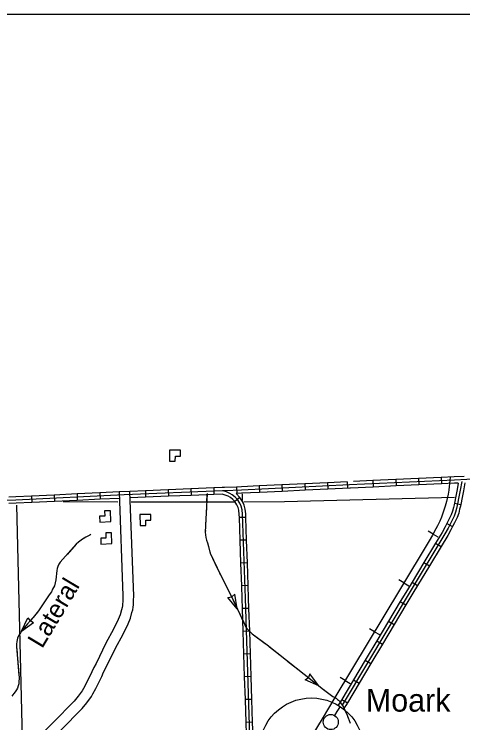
# Model space of a CAD drawing. Extents: x 1164457 to 1439835, y 1590918 to 1773502.
# Drawn here: x 1308056 to 1318450, y 1662145 to 1678582 of the extents above; entities that cross this region are included whole.
import ezdxf

# ---------------------------------------------------------------- set-up
doc = ezdxf.new("R2010")
doc.units = 0
for name, color, linetype in [('Level 15', 7, 'Continuous'), ('Level 24', 7, 'Continuous'), ('Level 32', 7, 'Continuous'), ('Level 4', 7, 'Continuous'), ('Level 40', 7, 'Continuous'), ('Level 43', 7, 'Continuous'), ('Level 5', 7, 'Continuous'), ('Level 58', 7, 'Continuous'), ('Level 63', 7, 'Continuous'), ('R_Draft', 7, 'Continuous')]:
    doc.layers.add(name, color=color, linetype=linetype)

msp = doc.modelspace()

# ---------------------------------------------------------------- linework, layer by layer
at = {"layer": 'Level 15'}
for points in [[(1310735, 1667512), (1310486, 1667501), (1310577, 1665087), (1310573, 1664999), (1310572, 1664954), (1310569, 1664906), (1310564, 1664860), (1310557, 1664818), (1310544, 1664765), (1310512, 1664653), (1310467, 1664540), (1310358, 1664316), (1310183, 1663994), (1309952, 1663519), (1309902, 1663427), (1309857, 1663325), (1309726, 1663054), (1309664, 1662942), (1309634, 1662890), (1309542, 1662760), (1309448, 1662647), (1308959, 1662152), (1307801, 1660969), (1308163, 1660982)], [(1308163, 1660982), (1309138, 1661977), (1309634, 1662478), (1309741, 1662607), (1309845, 1662755), (1309882, 1662819), (1309948, 1662939), (1310084, 1663220), (1310127, 1663317), (1310174, 1663405), (1310405, 1663880), (1310580, 1664202), (1310696, 1664438), (1310749, 1664572), (1310785, 1664701), (1310802, 1664768), (1310812, 1664827), (1310818, 1664884), (1310822, 1664943), (1310822, 1664992), (1310828, 1665085), (1310735, 1667512)]]:
    msp.add_lwpolyline(points, dxfattribs=at)
at = {"layer": 'Level 24'}
msp.add_circle((1315391, 1662163), 175, dxfattribs=at)
at = {"layer": 'Level 32'}
for p, q in [((1314787, 1667690), (1314794, 1667540)), ((1315314, 1667715), (1315321, 1667565)), ((1315768, 1667737), (1315775, 1667587)), ((1316369, 1667765), (1316376, 1667615)), ((1316897, 1667789), (1316903, 1667639)), ((1317424, 1667813), (1317431, 1667663)), ((1317952, 1667837), (1317958, 1667687)), ((1311095, 1667527), (1311101, 1667377)), ((1311622, 1667549), (1311629, 1667399)), ((1312150, 1667571), (1312156, 1667421)), ((1312678, 1667593), (1312684, 1667443)), ((1313205, 1667614), (1313211, 1667464)), ((1313732, 1667639), (1313739, 1667489)), ((1314259, 1667664), (1314267, 1667514)), ((1308457, 1667404), (1308464, 1667254)), ((1308985, 1667429), (1308992, 1667280)), ((1309512, 1667455), (1309519, 1667305)), ((1310039, 1667480), (1310047, 1667330)), ((1313286, 1667371), (1313168, 1667277)), ((1318256, 1667242), (1318402, 1667207)), ((1313424, 1666911), (1313274, 1666906)), ((1318080, 1666765), (1318214, 1666698)), ((1313441, 1666383), (1313292, 1666378)), ((1317821, 1666312), (1317949, 1666235)), ((1313459, 1665855), (1313309, 1665850)), ((1317547, 1665861), (1317675, 1665783)), ((1317273, 1665409), (1317402, 1665331)), ((1313477, 1665328), (1313327, 1665322)), ((1317001, 1664956), (1317130, 1664879)), ((1313494, 1664800), (1313344, 1664795)), ((1316731, 1664503), (1316860, 1664426)), ((1313512, 1664272), (1313362, 1664267)), ((1316460, 1664049), (1316589, 1663972)), ((1313529, 1663744), (1313379, 1663739)), ((1316190, 1663596), (1316318, 1663519)), ((1313546, 1663217), (1313396, 1663212)), ((1315919, 1663143), (1316048, 1663066)), ((1313563, 1662689), (1313413, 1662684)), ((1315648, 1662689), (1315777, 1662612)), ((1313580, 1662161), (1313431, 1662156))]:
    msp.add_line(p, q, dxfattribs=at)
for points in [[(1321119, 1667917), (1318832, 1667801), (1318254, 1667775), (1315826, 1667665), (1313323, 1667544), (1312931, 1667528), (1312880, 1667526), (1310607, 1667432), (1308095, 1667312), (1306907, 1667268), (1305501, 1667210), (1305435, 1667209), (1305218, 1667203), (1302807, 1667104), (1300037, 1666964), (1300001, 1666961)], [(1318479, 1667860), (1318251, 1667850), (1317952, 1667837)], [(1314787, 1667690), (1314259, 1667664)], [(1315314, 1667715), (1314787, 1667690)], [(1315768, 1667737), (1315314, 1667715)], [(1318424, 1667744), (1318392, 1667540), (1318354, 1667350), (1318338, 1667262), (1318320, 1667187), (1318304, 1667119), (1318283, 1667032), (1318248, 1666938), (1318188, 1666814), (1318110, 1666658), (1318037, 1666525), (1317230, 1665193), (1315703, 1662634), (1315655, 1662557)], [(1316369, 1667765), (1315918, 1667744)], [(1316897, 1667789), (1316369, 1667765)], [(1317424, 1667813), (1316897, 1667789)], [(1317952, 1667837), (1317424, 1667813)], [(1318342, 1667704), (1318258, 1667701), (1317958, 1667687)], [(1318342, 1667704), (1318318, 1667554), (1318280, 1667364), (1318264, 1667278), (1318256, 1667242)], [(1318494, 1667711), (1318466, 1667527), (1318427, 1667335), (1318411, 1667247), (1318402, 1667207)], [(1311095, 1667527), (1310735, 1667512)], [(1311622, 1667549), (1311095, 1667527)], [(1312150, 1667571), (1311622, 1667549)], [(1312678, 1667593), (1312150, 1667571)], [(1313205, 1667614), (1312928, 1667603), (1312878, 1667601), (1312678, 1667593)], [(1313540, 1661103), (1313412, 1665035), (1313346, 1666984), (1313336, 1667088), (1313314, 1667167), (1313281, 1667242), (1313227, 1667324), (1313175, 1667379), (1313107, 1667431), (1313050, 1667466), (1312974, 1667500), (1312880, 1667526)], [(1313732, 1667639), (1313320, 1667619), (1313205, 1667614)], [(1314259, 1667664), (1313732, 1667639)], [(1314794, 1667540), (1314267, 1667514)], [(1315321, 1667565), (1314794, 1667540)], [(1315849, 1667591), (1315830, 1667590), (1315321, 1667565)], [(1316376, 1667615), (1315849, 1667591)], [(1316903, 1667639), (1316376, 1667615)], [(1317431, 1667663), (1316903, 1667639)], [(1317958, 1667687), (1317431, 1667663)], [(1308457, 1667404), (1308092, 1667387), (1307931, 1667381)], [(1308985, 1667429), (1308457, 1667404)], [(1309512, 1667455), (1308985, 1667429)], [(1310039, 1667480), (1309512, 1667455)], [(1310486, 1667501), (1310039, 1667480)], [(1311101, 1667377), (1310741, 1667363)], [(1311629, 1667399), (1311101, 1667377)], [(1312156, 1667421), (1311629, 1667399)], [(1312684, 1667443), (1312156, 1667421)], [(1312872, 1667451), (1312684, 1667443)], [(1313121, 1667325), (1313065, 1667369), (1313015, 1667400), (1312948, 1667429), (1312872, 1667451)], [(1313739, 1667489), (1313326, 1667469), (1313198, 1667464)], [(1313424, 1666911), (1313421, 1666989), (1313410, 1667102), (1313385, 1667193), (1313347, 1667278), (1313286, 1667371), (1313198, 1667464)], [(1314267, 1667514), (1313739, 1667489)], [(1308464, 1667254), (1308099, 1667237), (1307936, 1667231)], [(1308992, 1667280), (1308464, 1667254)], [(1309519, 1667305), (1308992, 1667280)], [(1310047, 1667330), (1309519, 1667305)], [(1310491, 1667351), (1310047, 1667330)], [(1313274, 1666906), (1313271, 1666979), (1313262, 1667074), (1313244, 1667142), (1313215, 1667205), (1313168, 1667277), (1313125, 1667323), (1313121, 1667325)], [(1318256, 1667242), (1318247, 1667204), (1318231, 1667136), (1318211, 1667054), (1318179, 1666967), (1318121, 1666847), (1318080, 1666765)], [(1318402, 1667207), (1318393, 1667170), (1318377, 1667102), (1318355, 1667010), (1318317, 1666908), (1318256, 1666781), (1318214, 1666698)], [(1313292, 1666378), (1313274, 1666906)], [(1313441, 1666383), (1313424, 1666911)], [(1318080, 1666765), (1318043, 1666693), (1317972, 1666562), (1317821, 1666312)], [(1318214, 1666698), (1318176, 1666623), (1318102, 1666487), (1317949, 1666235)], [(1313309, 1665850), (1313292, 1666378)], [(1313459, 1665855), (1313441, 1666383)], [(1317821, 1666312), (1317547, 1665861)], [(1317949, 1666235), (1317675, 1665783)], [(1313327, 1665322), (1313309, 1665850)], [(1313477, 1665328), (1313459, 1665855)], [(1317547, 1665861), (1317273, 1665409)], [(1317675, 1665783), (1317402, 1665331)], [(1317273, 1665409), (1317166, 1665232), (1317001, 1664956)], [(1313344, 1664795), (1313337, 1665032), (1313327, 1665322)], [(1313494, 1664800), (1313487, 1665037), (1313477, 1665328)], [(1317402, 1665331), (1317295, 1665154), (1317130, 1664879)], [(1317001, 1664956), (1316731, 1664503)], [(1313362, 1664267), (1313344, 1664795)], [(1313512, 1664272), (1313494, 1664800)], [(1317130, 1664879), (1316860, 1664426)], [(1316731, 1664503), (1316460, 1664049)], [(1316860, 1664426), (1316589, 1663972)], [(1313379, 1663739), (1313362, 1664267)], [(1313529, 1663744), (1313512, 1664272)], [(1316460, 1664049), (1316190, 1663596)], [(1316589, 1663972), (1316318, 1663519)], [(1313546, 1663217), (1313529, 1663744)], [(1313396, 1663212), (1313379, 1663739)], [(1316190, 1663596), (1315919, 1663143)], [(1316318, 1663519), (1316048, 1663066)], [(1313413, 1662684), (1313396, 1663212)], [(1313563, 1662689), (1313546, 1663217)], [(1315919, 1663143), (1315648, 1662689)], [(1316048, 1663066), (1315777, 1662612)], [(1313431, 1662156), (1313413, 1662684)], [(1313580, 1662161), (1313563, 1662689)], [(1315648, 1662689), (1315639, 1662673), (1315563, 1662551)], [(1315777, 1662612), (1315767, 1662595), (1315686, 1662466)], [(1315607, 1662524), (1315535, 1662409), (1315479, 1662314)], [(1313448, 1661629), (1313431, 1662156)], [(1313598, 1661633), (1313580, 1662161)]]:
    msp.add_lwpolyline(points, dxfattribs=at)
at = {"layer": 'Level 4'}
for points in [[(1318256, 1667372), (1314316, 1667274), (1313380, 1667260)], [(1310461, 1667266), (1309195, 1667269)], [(1313155, 1667260), (1310768, 1667266)]]:
    msp.add_lwpolyline(points, dxfattribs=at)
at = {"layer": 'Level 40'}
for p, q in [((1317760, 1666523), (1317645, 1666589)), ((1317760, 1666523), (1317874, 1666458)), ((1317083, 1665390), (1316970, 1665458)), ((1317083, 1665390), (1317196, 1665322)), ((1316404, 1664258), (1316291, 1664326)), ((1316404, 1664258), (1316517, 1664190)), ((1315725, 1663126), (1315612, 1663194)), ((1315725, 1663126), (1315839, 1663058))]:
    msp.add_line(p, q, dxfattribs=at)
for points in [[(1318160, 1667846), (1318145, 1667692), (1318137, 1667625), (1318127, 1667544), (1318111, 1667447), (1318075, 1667282), (1318044, 1667169), (1318005, 1667052), (1317953, 1666912), (1317914, 1666819), (1317861, 1666718), (1317827, 1666642), (1317746, 1666499), (1317671, 1666370), (1317004, 1665258), (1315488, 1662729), (1315190, 1662240), (1314758, 1661525)], [(1318153, 1667771), (1318145, 1667692), (1318137, 1667625), (1318127, 1667544), (1318111, 1667447), (1318075, 1667282), (1318044, 1667169), (1318005, 1667052), (1317953, 1666912), (1317914, 1666819), (1317861, 1666718), (1317827, 1666642), (1317746, 1666499), (1317671, 1666370), (1317004, 1665258), (1315488, 1662729), (1315190, 1662240), (1314758, 1661525)]]:
    msp.add_lwpolyline(points, dxfattribs=at)
at = {"layer": 'Level 43'}
for p, q in [((1313005, 1665051), (1313095, 1665067)), ((1313166, 1665126), (1313096, 1665067)), ((1313225, 1664788), (1313166, 1665126)), ((1313225, 1664788), (1313005, 1665051)), ((1308223, 1664274), (1308370, 1664584)), ((1308372, 1664584), (1308423, 1664508)), ((1308223, 1664274), (1308505, 1664469)), ((1308506, 1664467), (1308424, 1664507)), ((1314908, 1663279), (1314872, 1663195)), ((1315115, 1663006), (1314908, 1663279)), ((1314799, 1663139), (1314872, 1663194)), ((1315115, 1663006), (1314799, 1663139))]:
    msp.add_line(p, q, dxfattribs=at)
for points in [[(1312524, 1667465), (1312484, 1666566), (1312490, 1666505), (1312497, 1666445), (1312513, 1666381), (1312536, 1666323), (1312597, 1666080), (1312834, 1665580), (1313085, 1665088), (1313373, 1664471), (1313426, 1664364), (1313482, 1664295), (1313567, 1664207), (1313916, 1663951), (1315226, 1662919), (1315408, 1662778), (1315439, 1662759), (1315521, 1662708), (1315515, 1662712)], [(1312523, 1667436), (1312515, 1667268)], [(1312509, 1667136), (1312492, 1666740)], [(1312486, 1666608), (1312484, 1666566), (1312490, 1666505), (1312497, 1666445), (1312513, 1666381), (1312536, 1666323), (1312561, 1666222)], [(1309830, 1666510), (1309809, 1666500), (1309717, 1666455), (1309637, 1666402), (1309549, 1666339), (1309492, 1666288), (1309122, 1665868), (1309088, 1665822), (1309064, 1665768), (1309055, 1665721), (1309046, 1665675), (1309025, 1665458), (1308987, 1665320), (1308946, 1665246), (1308920, 1665187), (1308869, 1665112), (1308621, 1664741), (1308561, 1664666), (1308494, 1664588), (1308436, 1664522), (1308365, 1664440), (1308293, 1664356), (1308243, 1664299), (1308201, 1664236), (1308159, 1664163), (1308137, 1664105), (1308114, 1664034), (1308110, 1663968), (1308113, 1663911), (1308169, 1663188), (1308166, 1663089), (1308163, 1663048), (1308149, 1663000), (1308131, 1662950), (1308110, 1662912), (1308079, 1662865), (1308052, 1662827)], [(1309830, 1666510), (1309809, 1666500), (1309717, 1666455), (1309656, 1666415)], [(1309549, 1666339), (1309549, 1666339), (1309492, 1666288), (1309280, 1666048)], [(1312593, 1666094), (1312597, 1666080), (1312760, 1665736)], [(1309193, 1665949), (1309122, 1665868), (1309088, 1665822), (1309064, 1665768), (1309055, 1665721), (1309046, 1665675), (1309039, 1665598)], [(1312816, 1665616), (1312834, 1665580), (1312996, 1665263)], [(1309026, 1665467), (1309025, 1665458), (1308987, 1665320), (1308946, 1665246), (1308920, 1665187), (1308869, 1665112), (1308867, 1665108)], [(1313056, 1665146), (1313085, 1665088), (1313225, 1664788)], [(1308793, 1664999), (1308621, 1664741), (1308567, 1664674)], [(1308481, 1664574), (1308436, 1664522), (1308365, 1664440), (1308293, 1664356), (1308243, 1664299), (1308225, 1664272)], [(1313281, 1664668), (1313354, 1664513)], [(1308158, 1664159), (1308137, 1664105), (1308114, 1664034), (1308110, 1663968)], [(1313553, 1664221), (1313567, 1664207), (1313870, 1663985)], [(1308110, 1663968), (1308110, 1663968), (1308113, 1663911), (1308124, 1663771)], [(1313975, 1663905), (1314286, 1663660)], [(1308134, 1663639), (1308165, 1663244)], [(1314390, 1663578), (1314701, 1663333)], [(1314804, 1663251), (1315115, 1663006)], [(1308167, 1663113), (1308166, 1663089), (1308163, 1663048), (1308149, 1663000), (1308131, 1662950), (1308110, 1662912), (1308079, 1662865), (1308052, 1662827), (1308024, 1662791), (1307999, 1662765)], [(1315219, 1662924), (1315226, 1662919), (1315408, 1662778), (1315439, 1662759), (1315488, 1662729)], [(1315521, 1662708), (1315548, 1662690), (1315572, 1662670), (1315595, 1662648), (1315612, 1662623), (1315632, 1662582), (1315664, 1662548), (1315683, 1662510), (1315734, 1662399), (1315767, 1662323), (1315841, 1662138)], [(1315715, 1662443), (1315767, 1662323), (1315793, 1662257)]]:
    msp.add_lwpolyline(points, dxfattribs=at)
at = {"layer": 'Level 5'}
for points in [[(1313347, 1667302), (1313344, 1667458)], [(1308113, 1667195), (1308246, 1661468)]]:
    msp.add_lwpolyline(points, dxfattribs=at)
at = {"layer": 'Level 58'}
for points in [[(1311658, 1668469), (1311655, 1668215), (1311789, 1668214), (1311790, 1668334), (1311910, 1668332), (1311912, 1668466)], [(1310293, 1666811), (1310285, 1667064), (1310151, 1667060), (1310155, 1666940), (1310035, 1666937), (1310039, 1666803)], [(1310969, 1666975), (1310972, 1666721), (1311106, 1666722), (1311105, 1666842), (1311225, 1666843), (1311223, 1666977)], [(1310321, 1666301), (1310312, 1666555), (1310178, 1666550), (1310183, 1666430), (1310063, 1666426), (1310067, 1666292)]]:
    msp.add_lwpolyline(points, close=True, dxfattribs=at)
at = {"layer": 'Level 63'}
msp.add_circle((1314944, 1661515), 1207, dxfattribs=at)
at = {"layer": 'R_Draft'}
msp.add_lwpolyline([(1246398, 1678582), (1349820, 1678582), (1349820, 1614471), (1246398, 1614471)], close=True, dxfattribs=at)

# ---------------------------------------------------------------- texts
at = {"layer": 'Level 24'}
msp.add_text('Moark', height=528, dxfattribs=at).set_placement((1316203, 1662405))
at = {"layer": 'Level 43'}
msp.add_text('Lateral', height=422, rotation=59.1086, dxfattribs=at).set_placement((1308703, 1663850))

doc.saveas('drawing.dxf')
